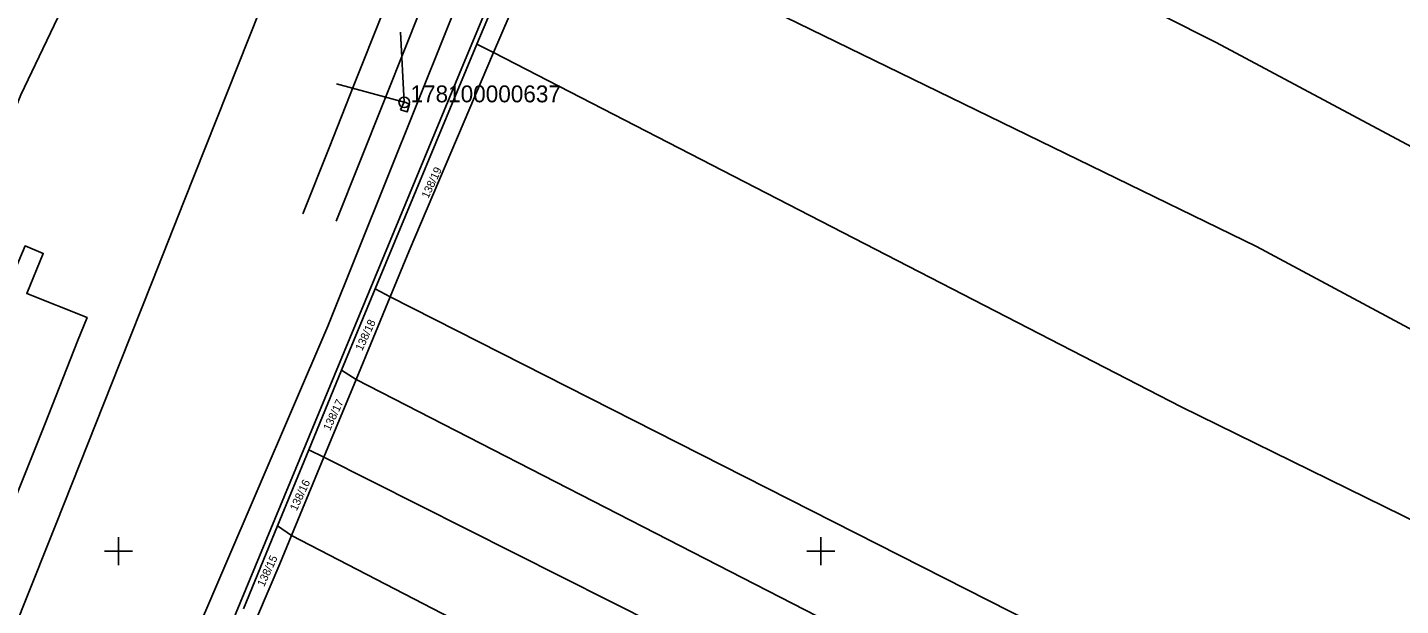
# Model space of a CAD drawing. Extents: x -755344 to -754412, y -1162670 to -1161477.
# Drawn here: x -754912.9 to -754717.5, y -1162307.8 to -1162225.4 of the extents above; entities that cross this region are included whole.
import ezdxf

# ---------------------------------------------------------------- set-up
doc = ezdxf.new("R2010")
doc.units = 0
for name, color, linetype in [('Body ŽBP', 7, 'Continuous'), ('Katastrální hranice', 7, 'Continuous'), ('Síť', 7, 'Continuous'), ('Vrstva 1', 7, 'Continuous'), ('Vrstva 12', 7, 'Continuous'), ('Vrstva 53', 7, 'Continuous'), ('Vrstva 55', 7, 'Continuous'), ('Vrstva 57', 7, 'Continuous')]:
    doc.layers.add(name, color=color, linetype=linetype)

msp = doc.modelspace()

# ---------------------------------------------------------------- linework, layer by layer
at = {"layer": 'Body ŽBP'}
for p, q in [((-754859.31, -1162236.08), (-754859.83, -1162226.09)), ((-754859.31, -1162236.08), (-754868.96, -1162233.46)), ((-754859.29, -1162236.03), (-754859.33, -1162236.13)), ((-754859.31, -1162236.08), (-754859.31, -1162236.08))]:
    msp.add_line(p, q, dxfattribs=at)
msp.add_circle((-754859.31, -1162236.08), 0.756, dxfattribs=at)
at = {"layer": 'Katastrální hranice'}
msp.add_lwpolyline([(-754816.22, -1162147.35), (-754851.45, -1162231.96), (-754887.61, -1162319.28), (-754904.19, -1162359.38)], dxfattribs=at)
at = {"layer": 'Síť'}
for points in [[(-754900, -1162298), (-754900, -1162300), (-754900, -1162302)], [(-754800, -1162298), (-754800, -1162300), (-754800, -1162302)], [(-754898, -1162300), (-754900, -1162300), (-754902, -1162300)], [(-754798, -1162300), (-754800, -1162300), (-754802, -1162300)]]:
    msp.add_lwpolyline(points, dxfattribs=at)
at = {"layer": 'Vrstva 1'}
for points in [[(-754868.98, -1162253.01), (-754858.91, -1162227.64), (-754849.55, -1162204.07), (-754841.17, -1162182.97), (-754832.59, -1162161.33)], [(-754873.74, -1162251.98), (-754870.01, -1162242.56), (-754866.47, -1162233.66), (-754862.36, -1162223.3), (-754858.77, -1162214.24), (-754855.13, -1162205.06)], [(-754903.04, -1162213.58), (-754907.06, -1162220.68), (-754913.9, -1162235.02), (-754920.39, -1162251.15)]]:
    msp.add_lwpolyline(points, dxfattribs=at)
at = {"layer": 'Vrstva 12'}
msp.add_lwpolyline([(-754859.82, -1162237.15), (-754858.9, -1162237.45), (-754858.57, -1162236.36), (-754859.34, -1162236), (-754859.82, -1162237.15)], dxfattribs=at)
at = {"layer": 'Vrstva 53'}
msp.add_lwpolyline([(-754717.5, -1161955.11), (-754731.42, -1161979.09), (-754747.41, -1161959.83), (-754749.74, -1161970.12), (-754750.32, -1161972.64), (-754745.89, -1161978.47), (-754747.84, -1161978.77), (-754754.27, -1161988.55), (-754756.33, -1161996.85), (-754760.29, -1162004.33), (-754789, -1162076.26), (-754793.13, -1162087.4), (-754798.15, -1162101.07), (-754802.96, -1162113.9), (-754816.22, -1162147.35), (-754851.45, -1162231.96), (-754887.61, -1162319.28)], dxfattribs=at)
at = {"layer": 'Vrstva 55'}
for p, q in [((-754848.96, -1162227.81), (-754840.13, -1162206.56)), ((-754837.67, -1162208.02), (-754846.58, -1162228.99)), ((-754863.44, -1162262.66), (-754848.96, -1162227.81)), ((-754846.58, -1162228.99), (-754848.96, -1162227.81)), ((-754868.25, -1162274.25), (-754863.44, -1162262.66)), ((-754861.29, -1162263.76), (-754866.17, -1162275.57)), ((-754861.29, -1162263.76), (-754863.44, -1162262.66)), ((-754872.9, -1162285.56), (-754868.25, -1162274.25)), ((-754866.17, -1162275.57), (-754868.25, -1162274.25)), ((-754866.17, -1162275.57), (-754870.74, -1162286.62)), ((-754877.36, -1162296.41), (-754872.9, -1162285.56)), ((-754870.74, -1162286.62), (-754872.9, -1162285.56)), ((-754870.74, -1162286.62), (-754875.34, -1162297.75)), ((-754882.21, -1162308.21), (-754877.36, -1162296.41)), ((-754875.34, -1162297.75), (-754877.36, -1162296.41))]:
    msp.add_line(p, q, dxfattribs=at)
for points in [[(-754978.01, -1162551.88), (-754981.37, -1162542.41), (-754930.02, -1162407.36), (-754870.17, -1162267.96), (-754836.4, -1162183.6), (-754824.89, -1162157.4), (-754808.97, -1162117.64), (-754790.52, -1162068.93), (-754761.32, -1161999.17), (-754754.27, -1161988.55)], [(-754816.22, -1162147.35), (-754851.45, -1162231.96), (-754887.61, -1162319.28), (-754904.19, -1162359.38)], [(-754816.22, -1162147.35), (-754851.45, -1162231.96), (-754887.61, -1162319.28), (-754904.19, -1162359.38)], [(-754827.93, -1162185.11), (-754743.71, -1162227.55), (-754668.64, -1162267.68), (-754640.75, -1162283.26)], [(-754837.67, -1162208.02), (-754737.97, -1162256.6), (-754682.13, -1162286.58), (-754649.24, -1162305.33)], [(-754878.41, -1162219.27), (-754890.63, -1162250.1), (-754895.21, -1162261.65), (-754899.8, -1162273.21), (-754904.37, -1162284.73), (-754908.92, -1162296.21), (-754913.49, -1162307.74), (-754920.81, -1162326.21)], [(-754846.58, -1162228.99), (-754858.59, -1162257.23), (-754861.29, -1162263.76)], [(-754657.78, -1162327.52), (-754706.68, -1162300.09), (-754748.68, -1162279.47), (-754846.58, -1162228.99)], [(-754922.63, -1162261.43), (-754921.01, -1162257.39), (-754914.72, -1162259.89), (-754913.29, -1162256.54), (-754910.69, -1162257.6), (-754913.05, -1162263.33), (-754904.47, -1162266.73), (-754905.81, -1162270.11), (-754910.45, -1162281.8), (-754914.62, -1162292.29), (-754930, -1162286.19), (-754925.41, -1162274.6), (-754922.38, -1162266.96), (-754924.5, -1162266.11), (-754922.63, -1162261.43)], [(-754861.29, -1162263.76), (-754731.98, -1162329.45), (-754719.33, -1162336.16), (-754671.23, -1162362.45)], [(-754866.17, -1162275.57), (-754759.65, -1162330.23), (-754738.88, -1162341.27)], [(-754870.74, -1162286.62), (-754762.18, -1162341.31), (-754743.7, -1162351.33)], [(-754875.34, -1162297.75), (-754877.03, -1162301.83), (-754880.18, -1162309.28)], [(-754875.34, -1162297.75), (-754796.43, -1162338.66), (-754749.36, -1162363.14)]]:
    msp.add_lwpolyline(points, dxfattribs=at)

# ---------------------------------------------------------------- texts
at = {"layer": 'Body ŽBP'}
msp.add_text(' 178100000637', height=2.4, dxfattribs=at).set_placement((-754859.31, -1162236.08))
at = {"layer": 'Vrstva 57'}
for s, p in [('138/19', (-754855.89, -1162249.86)), ('138/18', (-754865.3, -1162271.57)), ('138/17', (-754869.88, -1162282.94)), ('138/16', (-754874.63, -1162294.37)), ('138/15', (-754879.27, -1162305.16))]:
    msp.add_text(s, height=1.139, rotation=65, dxfattribs=at).set_placement(p)

doc.saveas('drawing.dxf')
